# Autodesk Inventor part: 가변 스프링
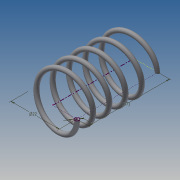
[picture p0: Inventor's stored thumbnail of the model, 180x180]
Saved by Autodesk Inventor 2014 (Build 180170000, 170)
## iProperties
Created: 2016-01
Part Number: 가변 스프링
Material: Generic
Document SubType Name: Modeling
Designer: Administrator
Density: 1 g/cm^3
Appearance: Default
Author: Administrator
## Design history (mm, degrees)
sketch "스케치1"
  geometry: L1 (0, 37)-(11, 37); L2 (11, 37)-(11, 0); L3 (11, 0)-(0, 0); L4 (0, 0)-(0, 37); C1 r 1 at (11, 0); 1 further point
  constraints: 8 end point, 2 coincident, 2 parallel, 1 centre point, 1 horizontal, 1 perpendicular
  dimensions: "d0" = 22 diameter of L2.end L4; "d1" = 37 distance of L1.end L2.end (derived); "d2" = 2 diameter of C1
feature "코일1" pitch "d3" = 10; turns "d5" = 5; dims "d4" = 37 (= d1), "d6" = 0, angle "d7" = 90 deg, angle "d8" = 90 deg, "d9" = 0, "d10" = 0
sketch "스케치2"
  geometry: L1 (-12, 0)-(-10, 0) reference; 1 further point
  constraints: 1 horizontal alignment
extrude "돌출1" cut sketch "스케치2" distance "d11" = 10; taper "d12" = 0 deg
node "작업 평면1"
sketch "스케치3"
  geometry: L1 (10, 0)-(12, 0) reference; 1 further point
  constraints: 1 horizontal alignment
extrude "돌출2" cut sketch "스케치3" distance "d14" = 10; taper "d15" = 0 deg
node "솔리드1"
node "절단 모서리 투영1"
node "절단 모서리 투영2"
other parameters: "d13" = 0
